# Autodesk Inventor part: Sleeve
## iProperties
Created: 2006-11
Part Number: Sleeve
Document SubType Name: Modeling
Designer: nfjf
Author: nfjf
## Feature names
1. Extrusion3
2. Extrusion4
3. Fillet2
4. Fillet3
5. Fillet4
6. Fillet5
7. Extrusion5
8. Fillet6
9. Extrusion6
10. Extrusion7
